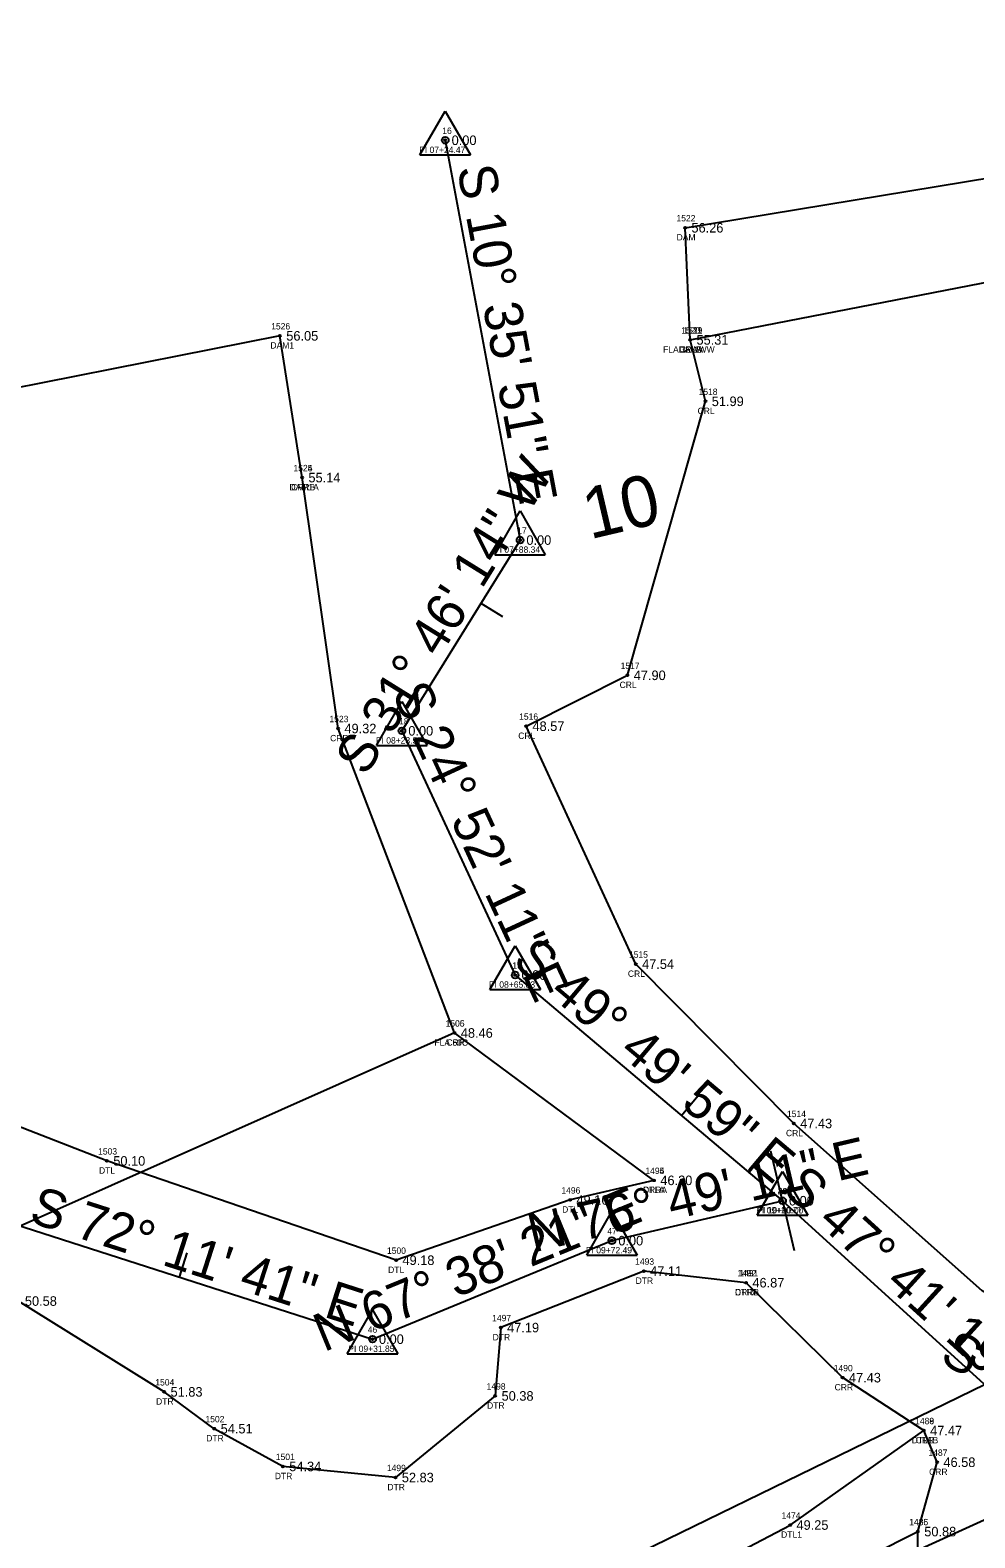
# Model space of a CAD drawing. Extents: x 2420113 to 2422887, y 845323 to 846653.
# Drawn here: x 2421599.8 to 2421748.2, y 845811.6 to 846048.3 of the extents above; entities that cross this region are included whole.
import ezdxf

# ---------------------------------------------------------------- set-up
doc = ezdxf.new("R2010")
doc.units = 0
for name, color, linetype in [('RD_EX_Dam', 7, 'Continuous'), ('RD_EX_Dam_txCode', 7, 'Continuous'), ('RD_EX_Fence_Other', 7, 'Continuous'), ('RD_EX_Fence_Other_txCode', 7, 'Continuous'), ('RD_EX_GuardRail', 7, 'Continuous'), ('RD_EX_H2O', 7, 'Continuous'), ('RD_EX_H2O_txCode', 7, 'Continuous'), ('RD_EX_TX_Dam_ELEV', 7, 'Continuous'), ('RD_EX_TX_Fence_Other_ELEV', 7, 'Continuous'), ('RD_EX_TX_H2O_ELEV', 7, 'Continuous'), ('RD_EX_VEG', 7, 'Continuous'), ('RD_HC_Cl', 7, 'Continuous'), ('RD_HC_Data', 7, 'Continuous'), ('RD_HC_Data_Tic', 7, 'Continuous'), ('RD_HC_Survey_ELEV', 7, 'Continuous'), ('RD_HC_TX_Sta50', 7, 'Continuous'), ('RD_HC_txCode', 7, 'Continuous'), ('RD_SMD_Locator', 7, 'Continuous')]:
    doc.layers.add(name, color=color, linetype=linetype)

msp = doc.modelspace()

# ---------------------------------------------------------------- linework, layer by layer
at = {"layer": 'RD_EX_Dam'}
for points in [[(2421703.45, 845999.67), (2421702.66, 846017.28), (2421795.13, 846032.49), (2421876.44, 846046.05), (2421920.78, 846055.77), (2422010.13, 846069.83), (2422010.13, 846069.83), (2422059.48, 846081.4), (2422106.12, 846132.59), (2422121.56, 846164.68), (2422122.27, 846182.92)], [(2421642.53, 845978.05), (2421639.05, 846000.31), (2421580.85, 845988.77), (2421535.07, 845982.51), (2421515.21, 845982.5), (2421497.5, 845976.94), (2421503.44, 845954.37)]]:
    msp.add_lwpolyline(points, dxfattribs=at)
at = {"layer": 'RD_EX_Fence_Other'}
msp.add_line((2421666.45, 845890.85), (2421566.2, 845846.23), dxfattribs=at)
msp.add_lwpolyline([(2421703.45, 845999.67), (2421880.76, 846034.16), (2421923.19, 846041.45), (2421955.6, 846044.92), (2421955.6, 846044.92), (2422030.66, 846058.97), (2422067.33, 846068.59), (2422121.12, 846101.59), (2422197.08, 846166.53), (2422266.9, 846224.55), (2422276.32, 846233.3)], dxfattribs=at)
at = {"layer": 'RD_EX_GuardRail'}
msp.add_lwpolyline([(2421687.56, 845786.15), (2421753.19, 845816.01), (2421776.46, 845828.5), (2421792.19, 845836.93), (2421803.2, 845843.9), (2421853.09, 845876.29)], dxfattribs=at)
at = {"layer": 'RD_EX_H2O'}
for points in [[(2420975.55, 846190.58), (2420976.37, 846105.11), (2420974.31, 845997.82), (2420976.03, 845896.74), (2420974.59, 845794.18), (2420975.37, 845743.63), (2420984.12, 845720.99), (2420999.91, 845711.18), (2421116.7, 845699.77), (2421177.35, 845696.01), (2421236.57, 845694.11), (2421292.07, 845694.75), (2421349.67, 845700.43), (2421411.57, 845706.56), (2421470.63, 845718.76), (2421529.96, 845732.93), (2421551.14, 845737.51), (2421602.97, 845753.33), (2421656.85, 845776.48), (2421724.45, 845805.15), (2421739.21, 845812.56)], [(2421712.23, 845851.64), (2421696.17, 845853.46), (2421673.72, 845844.59), (2421672.85, 845833.86), (2421657.19, 845821.05), (2421639.52, 845822.79), (2421628.75, 845828.72), (2421620.88, 845834.5), (2421598.01, 845848.76), (2421559.66, 845849.82), (2421519.66, 845839.33), (2421490.26, 845831.77), (2421489.16, 845834.56), (2421488.34, 845838.76), (2421481.47, 845840.1), (2421478.52, 845840.67), (2421462.88, 845836.78), (2421401.68, 845880.53), (2421390.37, 845914.71), (2421413.41, 845969.29), (2421455.53, 845995.93), (2421500.71, 846029.14), (2421506.65, 846045.11), (2421509.82, 846047.43)], [(2421697.78, 845867.71), (2421684.61, 845864.63), (2421657.29, 845855.17), (2421611.89, 845870.76), (2421583.33, 845881.87), (2421549.84, 845871.2), (2421517.26, 845862.24), (2421475.01, 845867.75), (2421422.24, 845899.02), (2421422.38, 845924.44), (2421434.43, 845964.2), (2421465.61, 845987.89), (2421488.91, 845998.31), (2421509.34, 846009.28), (2421510.99, 846011.42)], [(2421803.88, 845842.86), (2421794.61, 845845.35), (2421789.35, 845845.31), (2421784.3, 845849.6), (2421763.68, 845842.08), (2421749.32, 845850.38), (2421719.73, 845876.64), (2421694.91, 845901.66), (2421677.7, 845939.02), (2421693.6, 845947.01), (2421705.85, 845990.03), (2421703.45, 845999.67)], [(2421697.78, 845867.71), (2421666.45, 845890.85), (2421648.18, 845938.65), (2421642.53, 845978.05)], [(2421739.21, 845808.11), (2421739.21, 845812.56), (2421742.22, 845823.45), (2421740.13, 845828.42), (2421727.39, 845836.73), (2421712.23, 845851.64)], [(2421348.44, 845711.4), (2421408.11, 845718.43), (2421468.58, 845729.77), (2421526.52, 845745.24), (2421541.81, 845745.64), (2421549.75, 845745.7), (2421570.45, 845751.87), (2421591.88, 845757.66), (2421599.3, 845765.73), (2421650.04, 845787.07), (2421668.02, 845786.79), (2421719.15, 845813.59), (2421740.13, 845828.42)]]:
    msp.add_lwpolyline(points, dxfattribs=at)
at = {"layer": 'RD_EX_VEG'}
msp.add_lwpolyline([(2420990.17, 846190.24), (2420988, 845998.32), (2421000.67, 845894.83), (2421039.72, 845794.91), (2421064.26, 845723.75), (2421180.05, 845716.6), (2421345.47, 845727.16), (2421407.77, 845719.99), (2421650.04, 845787.07), (2421772.66, 845846.85), (2421772.66, 845846.85), (2421889.56, 845912.24), (2422060.37, 846045.26), (2422197.94, 846165.23), (2422281.92, 846227.58), (2422364.58, 846286.67), (2422339.46, 846334.5)], dxfattribs=at)
at = {"layer": 'RD_HC_Cl'}
for p, q in [((2421665.01, 846031.02), (2421676.75, 845968.24)), ((2421676.75, 845968.24), (2421658.21, 845938.29)), ((2421658.21, 845938.29), (2421675.98, 845899.95)), ((2421675.98, 845899.95), (2421717.97, 845864.51)), ((2421691.18, 845858.24), (2421717.97, 845864.51)), ((2421717.97, 845864.51), (2421754.99, 845830.81)), ((2421593.05, 845862.22), (2421653.6, 845842.77)), ((2421653.6, 845842.77), (2421691.18, 845858.24))]:
    msp.add_line(p, q, dxfattribs=at)
msp.add_arc((2421235.71, 846823.95), 1145.56, 264.46476, 308.21213, dxfattribs=at)
at = {"layer": 'RD_HC_Data'}
for p, q in [((2421661.04, 846028.73), (2421665.01, 846035.61)), ((2421665.01, 846035.61), (2421668.98, 846028.73)), ((2421661.04, 846028.73), (2421668.98, 846028.73)), ((2421672.78, 845965.95), (2421676.76, 845972.83)), ((2421676.76, 845972.83), (2421680.72, 845965.95)), ((2421672.78, 845965.95), (2421680.72, 845965.95)), ((2421654.24, 845936), (2421658.21, 845942.88)), ((2421658.21, 845942.88), (2421662.18, 845936)), ((2421654.24, 845936), (2421662.18, 845936)), ((2421672.01, 845897.66), (2421675.98, 845904.54)), ((2421675.98, 845904.54), (2421679.95, 845897.66)), ((2421672.01, 845897.66), (2421679.95, 845897.66)), ((2421714, 845862.22), (2421717.97, 845869.09)), ((2421714, 845862.22), (2421717.97, 845869.09)), ((2421717.97, 845869.09), (2421721.94, 845862.22)), ((2421717.97, 845869.09), (2421721.94, 845862.22)), ((2421687.21, 845855.94), (2421691.18, 845862.82)), ((2421691.18, 845862.82), (2421695.15, 845855.94)), ((2421714, 845862.22), (2421721.94, 845862.22)), ((2421714, 845862.22), (2421721.94, 845862.22)), ((2421687.21, 845855.94), (2421695.15, 845855.94)), ((2421649.63, 845840.48), (2421653.6, 845847.36)), ((2421653.6, 845847.36), (2421657.57, 845840.48)), ((2421649.63, 845840.48), (2421657.57, 845840.48))]:
    msp.add_line(p, q, dxfattribs=at)
for centre in [(2421665.01, 846031.02), (2421676.75, 845968.24), (2421658.21, 845938.29), (2421675.98, 845899.95), (2421717.97, 845864.51), (2421717.97, 845864.51), (2421691.18, 845858.24), (2421653.6, 845842.77)]:
    msp.add_circle(centre, 0.529, dxfattribs=at)
at = {"layer": 'RD_HC_Data_Tic'}
for p, q in [((2421670.62, 845958.33), (2421674.02, 845956.22)), ((2421702.09, 845877.91), (2421704.67, 845880.96)), ((2421717.97, 845864.51), (2421716.14, 845872.3)), ((2421717.97, 845864.51), (2421719.79, 845856.72)), ((2421623.28, 845852.51), (2421624.5, 845856.32))]:
    msp.add_line(p, q, dxfattribs=at)
at = {"layer": 'RD_SMD_Locator'}
for centre in [(2421665.01, 846031.02), (2421702.66, 846017.28), (2421639.05, 846000.31), (2421703.45, 845999.67), (2421703.45, 845999.67), (2421703.45, 845999.67), (2421705.85, 845990.03), (2421642.53, 845978.05), (2421642.53, 845978.05), (2421676.75, 845968.24), (2421693.6, 845947.01), (2421648.18, 845938.65), (2421677.7, 845939.02), (2421658.21, 845938.29), (2421694.91, 845901.66), (2421675.98, 845899.95), (2421666.45, 845890.85), (2421666.45, 845890.85), (2421719.73, 845876.64), (2421611.89, 845870.76), (2421697.78, 845867.71), (2421697.78, 845867.71), (2421684.61, 845864.63), (2421717.97, 845864.51), (2421717.97, 845864.51), (2421691.18, 845858.24), (2421657.29, 845855.17), (2421696.17, 845853.46), (2421712.23, 845851.64), (2421712.23, 845851.64), (2421673.72, 845844.59), (2421653.6, 845842.77), (2421620.88, 845834.5), (2421727.39, 845836.73), (2421672.85, 845833.86), (2421628.75, 845828.72), (2421740.13, 845828.42), (2421740.13, 845828.42), (2421639.52, 845822.79), (2421742.22, 845823.45), (2421657.19, 845821.05), (2421719.15, 845813.59), (2421739.21, 845812.56), (2421739.21, 845812.56)]:
    msp.add_circle(centre, 0.15, dxfattribs=at)

# ---------------------------------------------------------------- texts
at = {"layer": 'RD_EX_Dam_txCode'}
for s, p in [('1522', (2421701.31, 846018.28)), ('DAM', (2421701.33, 846015.28)), ('1526', (2421637.68, 846001.31)), ('1521', (2421702.39, 846000.67)), ('DAM1', (2421637.56, 845998.31)), ('DAMA', (2421701.63, 845997.67)), ('1525', (2421641.18, 845979.05)), ('DAM1A', (2421640.55, 845976.05))]:
    msp.add_text(s, height=1, dxfattribs=at).set_placement(p)
at = {"layer": 'RD_EX_Fence_Other_txCode'}
for s, p in [('1520', (2421702.06, 846000.67)), ('FLA 36WWW', (2421699.21, 845997.67)), ('1506', (2421665.05, 845891.85)), ('FLA 60C', (2421663.31, 845888.85))]:
    msp.add_text(s, height=1, dxfattribs=at).set_placement(p)
at = {"layer": 'RD_EX_H2O_txCode'}
for s, p in [('1519', (2421702.39, 846000.67)), ('CRLB', (2421701.75, 845997.67)), ('1518', (2421704.78, 845991.03)), ('CRL', (2421704.62, 845988.03)), ('1524', (2421641.18, 845979.05)), ('CRRB', (2421640.81, 845976.05)), ('1517', (2421692.54, 845948.01)), ('CRL', (2421692.38, 845945.01)), ('1523', (2421646.83, 845939.65)), ('1516', (2421676.61, 845940.02)), ('CRR', (2421646.93, 845936.65)), ('CRL', (2421676.47, 845937.02)), ('1515', (2421693.85, 845902.66)), ('CRL', (2421693.68, 845899.66)), ('1505', (2421665.07, 845891.85)), ('CRR', (2421665.2, 845888.85)), ('1514', (2421718.66, 845877.64)), ('CRL', (2421718.5, 845874.64)), ('1503', (2421610.51, 845871.76)), ('DTL', (2421610.65, 845868.76)), ('1494', (2421696.43, 845868.71)), ('1495', (2421696.43, 845868.71)), ('1496', (2421683.24, 845865.63)), ('CRRA', (2421696.04, 845865.71)), ('DTLA', (2421696.05, 845865.71)), ('DTL', (2421683.36, 845862.63)), ('1500', (2421655.86, 845856.17)), ('DTL', (2421656.04, 845853.17)), ('1493', (2421694.82, 845854.46)), ('1492', (2421710.88, 845852.64)), ('1491', (2421711.17, 845852.64)), ('DTR', (2421694.9, 845851.46)), ('CRRB', (2421710.5, 845849.64)), ('DTRA', (2421710.47, 845849.64)), ('1497', (2421672.37, 845845.59)), ('DTR', (2421672.45, 845842.59)), ('1490', (2421726, 845837.73)), ('1504', (2421619.49, 845835.5)), ('1498', (2421671.5, 845834.86)), ('CRR', (2421726.14, 845834.73)), ('DTR', (2421619.61, 845832.5)), ('DTR', (2421671.58, 845831.86)), ('1502', (2421627.36, 845829.72)), ('1488', (2421738.78, 845829.42)), ('1489', (2421738.78, 845829.42)), ('DTR', (2421627.48, 845826.72)), ('DTL1B', (2421738.25, 845826.42)), ('CRR', (2421738.87, 845826.42)), ('1487', (2421740.87, 845824.45)), ('1501', (2421638.41, 845823.79)), ('1499', (2421655.84, 845822.05)), ('DTR', (2421638.25, 845820.79)), ('CRR', (2421740.97, 845821.45)), ('DTR', (2421655.92, 845819.05)), ('1474', (2421717.81, 845814.59)), ('1486', (2421737.84, 845813.56)), ('1485', (2421737.86, 845813.56)), ('DTL1', (2421717.74, 845811.59))]:
    msp.add_text(s, height=1, dxfattribs=at).set_placement(p)
at = {"layer": 'RD_EX_TX_Dam_ELEV'}
for s, p in [('56.26', (2421703.66, 846016.53)), ('56.05', (2421640.05, 845999.56)), ('55.31', (2421704.45, 845998.92)), ('55.14', (2421643.53, 845977.3))]:
    msp.add_text(s, height=1.5, dxfattribs=at).set_placement(p)
at = {"layer": 'RD_EX_TX_Fence_Other_ELEV'}
for s, p in [('55.31', (2421704.45, 845998.92)), ('48.46', (2421667.45, 845890.1))]:
    msp.add_text(s, height=1.5, dxfattribs=at).set_placement(p)
at = {"layer": 'RD_EX_TX_H2O_ELEV'}
for s, p in [('55.31', (2421704.45, 845998.92)), ('51.99', (2421706.85, 845989.28)), ('55.14', (2421643.53, 845977.3)), ('47.90', (2421694.6, 845946.26)), ('49.32', (2421649.18, 845937.9)), ('48.57', (2421678.7, 845938.27)), ('47.54', (2421695.91, 845900.91)), ('48.46', (2421667.45, 845890.1)), ('47.43', (2421720.73, 845875.89)), ('50.10', (2421612.89, 845870.01)), ('46.20', (2421698.78, 845866.96)), ('46.20', (2421698.78, 845866.96)), ('49.16', (2421685.61, 845863.88)), ('49.18', (2421658.29, 845854.42)), ('47.11', (2421697.17, 845852.71)), ('46.87', (2421713.23, 845850.89)), ('46.87', (2421713.23, 845850.89)), ('50.58', (2421599.01, 845848.01)), ('47.19', (2421674.72, 845843.84)), ('47.43', (2421728.39, 845835.98)), ('51.83', (2421621.88, 845833.75)), ('50.38', (2421673.85, 845833.11)), ('54.51', (2421629.75, 845827.97)), ('47.47', (2421741.13, 845827.67)), ('47.47', (2421741.13, 845827.67)), ('54.34', (2421640.52, 845822.04)), ('46.58', (2421743.22, 845822.7)), ('52.83', (2421658.19, 845820.3)), ('49.25', (2421720.15, 845812.84)), ('50.88', (2421740.21, 845811.81)), ('50.88', (2421740.21, 845811.81))]:
    msp.add_text(s, height=1.5, dxfattribs=at).set_placement(p)
at = {"layer": 'RD_HC_Data'}
for s, rotation, p in [('S 10%%d 35\' 51" E', 280.5976, (2421666.85, 846026.63)), ('S 31%%d 46\' 14" W', 58.2293, (2421652.51, 845931)), ('S 24%%d 52\' 11" E', 294.8697, (2421656.55, 845944.25)), ('S 49%%d 49\' 59" E', 319.8332, (2421675.36, 845901.78)), ('N 76%%d 49\' 11" E', 13.1803, (2421678.8, 845856.36)), ('S 47%%d 41\' 19" E', 317.6887, (2421717.68, 845866.13)), ('S 72%%d 11\' 41" E', 342.1947, (2421599.45, 845861.21)), ('N 67%%d 38\' 21" E', 22.3608, (2421645.95, 845840.71)), ('S 59%%d 32\' 49" E', 329.5471, (2421742.43, 845839.35))]:
    msp.add_text(s, height=6, rotation=rotation, dxfattribs=at).set_placement(p)
at = {"layer": 'RD_HC_Survey_ELEV'}
for p in [(2421666.01, 846030.27), (2421677.75, 845967.49), (2421659.21, 845937.54), (2421676.98, 845899.2), (2421718.97, 845863.76), (2421718.97, 845863.76), (2421692.18, 845857.49), (2421654.6, 845842.02)]:
    msp.add_text('0.00', height=1.5, dxfattribs=at).set_placement(p)
at = {"layer": 'RD_HC_TX_Sta50'}
msp.add_text('10', height=8, rotation=13.1803, dxfattribs=at).set_placement((2421687.7, 845968.34))
at = {"layer": 'RD_HC_txCode'}
for s, p in [('16', (2421664.54, 846032.02)), ('PI 07+24.47', (2421660.91, 846029.02)), ('17', (2421676.31, 845969.24)), ('PI 07+88.34', (2421672.65, 845966.24)), ('18', (2421657.76, 845939.29)), ('PI 08+23.57', (2421654.11, 845936.29)), ('19', (2421675.53, 845900.95)), ('PI 08+65.83', (2421671.86, 845897.95)), ('20', (2421717.2, 845865.51)), ('48', (2421717.24, 845865.51)), ('PI 09+20.77', (2421713.83, 845862.51)), ('PI 10+00.00', (2421713.99, 845862.51)), ('47', (2421690.45, 845859.24)), ('PI 09+72.49', (2421687.08, 845856.24)), ('46', (2421652.84, 845843.77)), ('PI 09+31.85', (2421649.78, 845840.77))]:
    msp.add_text(s, height=1, dxfattribs=at).set_placement(p)

doc.saveas('drawing.dxf')
